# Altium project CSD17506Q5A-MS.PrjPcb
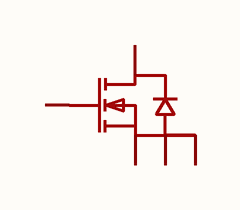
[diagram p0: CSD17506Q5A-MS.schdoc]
1 sheet, 1 parts. Net scope: global (net labels, ports and power ports of the same name join across sheets).

## Sheet CSD17506Q5A-MS.schdoc
size 127 x 101 mm

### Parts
Q?  csd17506q5a-ms  [TDSON-8_L5.9-W5.2-P1.27-BL-1]  (value not drawn)

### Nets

Not connected (* = marked no-connect by the designer): Q? 1(S) 2(S) 3(S) 4(G) 5(D)

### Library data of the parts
Q? = csd17506q5a-ms: 数量:1个N沟道;漏源电压(Vdss):30V;连续漏极电流(Id):90A;导通电阻(RDS(on)):3.5mΩ@10V;耗散功率(Pd):62.5W;阈值电压(Vgs(th)):1.5V;; Manufacturer: MSKSEMI(美森科); AddInBom: yes; ModelId: 6d3ef2b64d5a4f2dbd2ee02e0c7053d2; ModelTransform: 205.511,242.1255,0,0,0,0,0,42.913,0; Number: 1个N沟道; Drain to Source Voltage: 30V; Current - Continuous Drain(Id): 90A; Pd - Power Dissipation: 62.5W; Gate Threshold Voltage (Vgs(th)): 1.5V; Gate Charge(Qg): 45nC; Input Capacitance(Ciss): 2.1nF; Reverse Transfer Capacitance (Crss@Vds): 282pF; Type: N沟道; Output Capacitance(Coss): 326pF; Vgs: ±20V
